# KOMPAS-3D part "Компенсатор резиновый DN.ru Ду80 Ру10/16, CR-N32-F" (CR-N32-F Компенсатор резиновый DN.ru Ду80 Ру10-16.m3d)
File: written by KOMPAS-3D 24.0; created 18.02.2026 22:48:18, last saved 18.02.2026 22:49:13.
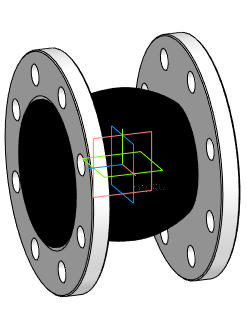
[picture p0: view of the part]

Document properties: Автор: DN.RU; Полное имя файла: D:\PROJECT CAD\DN.RU\...178(2)(ACTUALE). CR-N32-F Компенсатор резиновый DN.ru Ру10-16\CR-N32-F Компенсатор резиновый DN.ru Ру10-16\DN80\CR-N32-F Компенсатор резиновый DN.ru Ду80 Ру10-16 (2d).m3d

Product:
- Body: Твердое тело2  | qty 1
    Масса: 10.337867
- Part/product: Компенсатор резиновый DN.ru Ду80 Ру10/16  | designation CR-N32-F
    Масса: 7.5
    Раздел спецификации: Прочие изделия
    Комментарий: D140-02393
    Примечание: D140-02378
    additional columns: Типовые

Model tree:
1. Твердое тело2  (labels: Твердое тело2)

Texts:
  CR-N32-F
